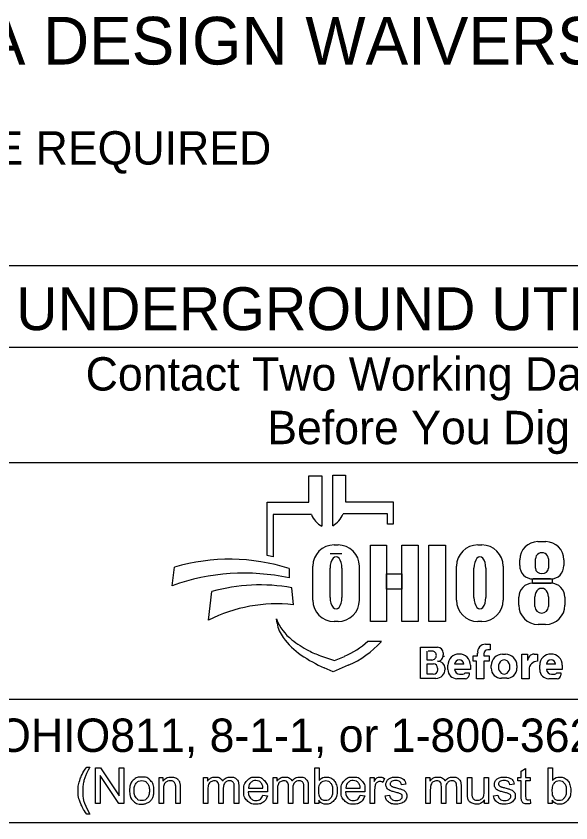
# Model space of a CAD drawing. Extents: x 0 to 34, y 0 to 22.
# Drawn here: x 2.506 to 4.831, y 2.01 to 5.395 of the extents above; entities that cross this region are included whole.
import ezdxf

# ---------------------------------------------------------------- set-up
doc = ezdxf.new("R2010")
doc.units = 0
doc.layers.add('SH_Data', color=7, linetype='Continuous')
doc.layers.add('SH_Text', color=7, linetype='Continuous')

msp = doc.modelspace()

# ---------------------------------------------------------------- linework, layer by layer
at = {"layer": 'SH_Data'}
for p, q in [((6.6275, 4.3472), (2.3775, 4.3472)), ((2.3775, 4.0056), (6.6275, 4.0056)), ((2.3775, 3.5222), (6.6275, 3.5222)), ((6.6275, 2.5276), (2.3775, 2.5276)), ((6.6275, 2.0097), (2.3775, 2.0097))]:
    msp.add_line(p, q, dxfattribs=at)
at = {"layer": 'SH_Text'}
for p, q in [((3.7335, 3.3552), (3.7335, 3.4667)), ((3.7335, 3.4667), (3.7872, 3.4667)), ((3.7872, 3.4667), (3.7872, 3.2546)), ((3.8329, 3.2569), (3.8329, 3.469)), ((3.8329, 3.469), (3.8865, 3.469)), ((3.8865, 3.469), (3.8865, 3.3575)), ((3.5576, 3.1313), (3.5576, 3.3552)), ((3.5576, 3.3552), (3.7335, 3.3552)), ((3.8865, 3.3575), (4.0857, 3.3575)), ((4.0857, 3.3575), (4.0857, 3.2637)), ((3.5828, 3.3038), (3.5828, 3.1269)), ((3.7439, 3.3038), (3.5828, 3.3038)), ((4.0625, 3.3061), (3.8761, 3.3061)), ((4.0625, 3.2637), (4.0625, 3.3061)), ((4.0857, 3.2637), (4.0625, 3.2637)), ((4.6931, 3.19), (4.7258, 3.19)), ((3.8385, 3.176), (3.8551, 3.176)), ((4.4416, 3.176), (4.4581, 3.176)), ((3.8718, 3.139), (3.822, 3.139)), ((4.683, 3.078), (4.683, 3.1173)), ((4.7371, 3.1173), (4.7371, 3.078)), ((3.1602, 3.005), (3.1696, 3.0831)), ((3.7491, 2.9445), (3.7491, 3.0865)), ((3.9445, 3.0865), (3.9445, 2.9445)), ((4.3521, 2.9445), (4.3521, 3.0865)), ((4.5476, 3.0865), (4.5476, 2.9445)), ((4.6168, 3.0894), (4.6168, 3.1137)), ((4.8022, 3.1137), (4.8022, 3.0894)), ((3.6509, 3.0766), (3.6509, 3.0378)), ((3.822, 2.9559), (3.822, 3.0783)), ((3.8718, 3.0783), (3.8718, 2.9559)), ((4.425, 2.9559), (4.425, 3.0783)), ((4.4748, 3.0783), (4.4748, 2.9559)), ((4.671, 3.0151), (4.7483, 3.0151)), ((4.7462, 3.0334), (4.6728, 3.0334)), ((3.312, 2.8605), (3.3267, 2.9806)), ((3.6608, 2.996), (3.6671, 2.9251)), ((4.6131, 2.9232), (4.6131, 2.9572)), ((4.6806, 2.9172), (4.6806, 2.9581)), ((4.7374, 2.9581), (4.7374, 2.9172)), ((4.8062, 2.9572), (4.8062, 2.9232)), ((3.5997, 2.8476), (3.5967, 2.8655)), ((3.8551, 2.8551), (3.8385, 2.8551)), ((4.4581, 2.8551), (4.4416, 2.8551)), ((4.7252, 2.8422), (4.6941, 2.8422)), ((3.98, 2.7717), (4.0375, 2.7717)), ((4.2013, 2.6159), (4.2013, 2.7467)), ((4.2013, 2.7467), (4.2725, 2.7467)), ((4.4739, 2.7595), (4.4934, 2.7595)), ((4.4934, 2.7595), (4.4934, 2.7365)), ((3.7816, 2.7113), (3.841, 2.6908)), ((4.2293, 2.6932), (4.2293, 2.7301)), ((4.2545, 2.7301), (4.2332, 2.7301)), ((4.2963, 2.7229), (4.2963, 2.715)), ((4.4213, 2.6881), (4.4213, 2.7111)), ((4.4213, 2.7111), (4.4406, 2.7111)), ((4.4406, 2.7111), (4.4406, 2.7215)), ((4.4667, 2.7195), (4.4667, 2.7111)), ((4.4667, 2.7111), (4.4883, 2.7111)), ((4.4934, 2.736), (4.4832, 2.736)), ((4.4883, 2.7111), (4.4883, 2.6881)), ((4.5451, 2.7177), (4.5573, 2.7177)), ((4.6254, 2.6147), (4.6254, 2.7174)), ((4.6254, 2.7174), (4.6499, 2.7174)), ((4.6499, 2.7174), (4.6499, 2.6906)), ((4.6772, 2.7174), (4.691, 2.7174)), ((4.691, 2.7174), (4.691, 2.6878)), ((3.841, 2.6908), (3.8821, 2.7086)), ((4.2487, 2.6932), (4.2293, 2.6932)), ((4.2293, 2.6338), (4.2293, 2.6766)), ((4.2293, 2.6766), (4.2548, 2.6766)), ((4.3824, 2.6751), (4.3439, 2.6751)), ((4.4362, 2.6881), (4.4213, 2.6881)), ((4.4362, 2.6147), (4.4362, 2.6881)), ((4.4883, 2.6881), (4.4667, 2.6881)), ((4.4667, 2.6881), (4.4667, 2.6147)), ((4.7674, 2.6751), (4.7288, 2.6751)), ((3.835, 2.6438), (3.7976, 2.6603)), ((3.8983, 2.6713), (3.835, 2.6438)), ((4.2729, 2.6585), (4.2729, 2.6522)), ((4.3043, 2.6556), (4.3043, 2.6553)), ((4.3159, 2.6527), (4.3159, 2.6711)), ((4.4104, 2.6535), (4.344, 2.6535)), ((4.4104, 2.6711), (4.4104, 2.6535)), ((4.4973, 2.6591), (4.4973, 2.6698)), ((4.6051, 2.6698), (4.6051, 2.6591)), ((4.6559, 2.6529), (4.6559, 2.6147)), ((4.7008, 2.6527), (4.7008, 2.6711)), ((4.7953, 2.6535), (4.7289, 2.6535)), ((4.7953, 2.6711), (4.7953, 2.6535)), ((4.265, 2.6159), (4.2013, 2.6159)), ((4.2546, 2.6338), (4.2293, 2.6338)), ((4.3892, 2.6147), (4.3538, 2.6147)), ((4.3649, 2.6342), (4.379, 2.6342)), ((4.3876, 2.6398), (4.4045, 2.6398)), ((4.4045, 2.6398), (4.4045, 2.63)), ((4.4667, 2.6147), (4.4362, 2.6147)), ((4.5623, 2.6163), (4.5401, 2.6163)), ((4.6559, 2.6147), (4.6254, 2.6147)), ((4.7742, 2.6147), (4.7388, 2.6147)), ((4.7498, 2.6342), (4.7639, 2.6342)), ((4.7725, 2.6398), (4.7894, 2.6398)), ((4.7894, 2.6398), (4.7894, 2.63))]:
    msp.add_line(p, q, dxfattribs=at)
for points in [[(3.991, 3.175), (4.0589, 3.175), (4.0589, 2.855), (3.991, 2.855)], [(4.1231, 3.175), (4.1911, 3.175), (4.1911, 2.855), (4.1231, 2.855)], [(4.2364, 3.175), (4.3052, 3.175), (4.3052, 2.855), (4.2364, 2.855)], [(4.0589, 3.0551), (4.1231, 3.0551), (4.1231, 2.9911), (4.0589, 2.9911)], [(4.6706, 3.0334), (4.7523, 3.0334), (4.7523, 3.015), (4.6706, 3.015)]]:
    msp.add_lwpolyline(points, close=True, dxfattribs=at)
for points in [[(2.8021, 2.2435), (2.8153, 2.2435)], [(2.8389, 2.0908), (2.8389, 2.241), (2.8592, 2.241), (2.9382, 2.123), (2.9382, 2.241), (2.9572, 2.241), (2.9572, 2.0908), (2.9369, 2.0908), (2.8579, 2.2088), (2.8579, 2.0908), (2.8389, 2.0908)], [(3.7743, 2.0908), (3.7573, 2.0908), (3.7573, 2.241), (3.7757, 2.241), (3.7757, 2.1875)], [(4.6233, 2.1227), (4.6233, 2.1854), (4.6097, 2.1854), (4.6097, 2.1997), (4.6233, 2.1997), (4.6233, 2.2266), (4.6417, 2.2377), (4.6417, 2.1997), (4.6601, 2.1997), (4.6601, 2.1854), (4.6417, 2.1854), (4.6417, 2.1216)], [(4.7534, 2.0908), (4.7363, 2.0908), (4.7363, 2.241), (4.7548, 2.241), (4.7548, 2.1875)], [(3.1048, 2.0908), (3.1048, 2.1997), (3.1214, 2.1997), (3.1214, 2.1842)], [(3.2912, 2.0908), (3.2912, 2.1997), (3.3077, 2.1997), (3.3077, 2.1843)], [(3.5826, 2.0908), (3.5826, 2.1997), (3.5991, 2.1997), (3.5991, 2.1843)], [(3.9904, 2.0908), (3.9904, 2.1997), (4.007, 2.1997), (4.007, 2.1832)], [(4.0495, 2.1962), (4.043, 2.1791)], [(4.1394, 2.1715), (4.1213, 2.1691)], [(4.2236, 2.0908), (4.2236, 2.1997), (4.2401, 2.1997), (4.2401, 2.1843)], [(4.3979, 2.1323), (4.3979, 2.1997), (4.4164, 2.1997), (4.4164, 2.1393)], [(4.4676, 2.1414), (4.4676, 2.1997), (4.4861, 2.1997), (4.4861, 2.0908), (4.4696, 2.0908)], [(4.594, 2.1715), (4.5759, 2.1691)], [(3.1233, 2.1502), (3.1233, 2.0908), (3.1048, 2.0908)], [(3.1932, 2.1577), (3.1932, 2.0908), (3.1748, 2.0908), (3.1748, 2.157)], [(3.3097, 2.1472), (3.3097, 2.0908), (3.2912, 2.0908)], [(3.3743, 2.154), (3.3743, 2.0908), (3.3559, 2.0908), (3.3559, 2.1615)], [(3.4388, 2.1655), (3.4388, 2.0908), (3.4203, 2.0908), (3.4203, 2.1593)], [(3.56, 2.1405), (3.4788, 2.1405)], [(3.4799, 2.1556), (3.5406, 2.1556)], [(3.601, 2.1472), (3.601, 2.0908), (3.5826, 2.0908)], [(3.6657, 2.154), (3.6657, 2.0908), (3.6473, 2.0908), (3.6473, 2.1615)], [(3.7301, 2.1655), (3.7301, 2.0908), (3.7117, 2.0908), (3.7117, 2.1593)], [(3.968, 2.1405), (3.8868, 2.1405)], [(3.8879, 2.1556), (3.9486, 2.1556)], [(4.0088, 2.1478), (4.0088, 2.0908), (3.9904, 2.0908)], [(4.242, 2.1472), (4.242, 2.0908), (4.2236, 2.0908)], [(4.3067, 2.154), (4.3067, 2.0908), (4.2883, 2.0908), (4.2883, 2.1615)], [(4.3711, 2.1655), (4.3711, 2.0908), (4.3527, 2.0908), (4.3527, 2.1593)], [(3.5404, 2.126), (3.5595, 2.1236)], [(3.7743, 2.1044), (3.7743, 2.0908)], [(3.9484, 2.126), (3.9675, 2.1236)], [(4.053, 2.1233), (4.0712, 2.1262)], [(4.4696, 2.0908), (4.4696, 2.1069)], [(4.5076, 2.1233), (4.5258, 2.1262)], [(4.6601, 2.1073), (4.6628, 2.091)], [(4.7534, 2.1044), (4.7534, 2.0908)], [(2.8153, 2.0466), (2.8021, 2.0466)]]:
    msp.add_lwpolyline(points, dxfattribs=at)
for centre, radius, start, end in [((3.8353, 3.3405), 0.0985, 201.9296, 240.7469), ((3.7847, 3.3429), 0.0985, 299.2531, 338.0704), ((4.6931, 3.1137), 0.0763, 90, 180), ((4.7258, 3.1137), 0.0763, 0, 90), ((3.8385, 3.0865), 0.0895, 90, 180), ((3.8551, 3.0865), 0.0895, 0, 90), ((4.4416, 3.0865), 0.0895, 90, 180), ((4.4581, 3.0865), 0.0895, 0, 90), ((3.3997, 2.2971), 0.8191, 72.1402, 106.3144), ((3.4295, 2.3223), 0.8191, 79.2074, 81.0007), ((4.6728, 3.0894), 0.056, 180, 270), ((4.7462, 3.0894), 0.056, 270, 0), ((3.4628, 2.1659), 0.8919, 77.8238, 109.8274), ((4.671, 2.9572), 0.0579, 90, 180), ((4.7483, 2.9572), 0.0579, 0, 90), ((3.5267, 2.2763), 0.7322, 79.44, 105.8467), ((3.5987, 2.2931), 0.6357, 83.8248, 116.8021), ((3.8385, 2.9445), 0.0895, 180, 270), ((3.8551, 2.9445), 0.0895, 270, 0), ((4.4416, 2.9445), 0.0895, 180, 270), ((4.4581, 2.9445), 0.0895, 270, 0), ((4.6941, 2.9232), 0.081, 180, 270), ((4.7252, 2.9232), 0.081, 270, 0), ((3.7841, 2.9376), 0.2008, 201.0457, 232.5314), ((3.741, 2.8717), 0.1433, 189.6817, 216.0884), ((3.8747, 2.9691), 0.3088, 216.0884, 235.7167), ((3.9766, 3.1888), 0.5173, 232.5314, 241.794), ((3.7387, 3.0391), 0.3602, 293.4582, 312.0712), ((3.7387, 3.0391), 0.401, 293.4582, 317.8286), ((4.2725, 2.7229), 0.0238, 0, 90), ((4.4739, 2.7259), 0.0335, 90, 187.5187), ((4.0412, 3.2134), 0.6044, 235.7167, 246.2325), ((3.8914, 3.03), 0.3371, 241.794, 250.9821), ((4.2487, 2.7119), 0.0187, 270, 2.0582), ((4.2505, 2.7132), 0.0169, 357.8325, 90), ((4.2721, 2.7122), 0.0243, 270, 6.6529), ((4.2827, 2.7107), 0.0175, 347.4023, 0), ((4.3631, 2.6711), 0.0473, 0, 180), ((4.4832, 2.7195), 0.0165, 90, 180), ((4.5451, 2.6698), 0.0478, 90, 180), ((4.5573, 2.6698), 0.0478, 0, 90), ((4.6768, 2.6906), 0.0269, 89.2449, 180), ((4.7481, 2.6711), 0.0473, 0, 180), ((4.2548, 2.6585), 0.0181, 0, 90), ((4.2722, 2.6558), 0.0321, 4.0748, 90), ((4.3632, 2.6741), 0.0193, 2.9632, 177.0368), ((4.6908, 2.6529), 0.0349, 89.6033, 180), ((4.7481, 2.6741), 0.0193, 2.9632, 177.0368), ((4.2546, 2.6522), 0.0184, 270, 0), ((4.265, 2.6553), 0.0393, 270, 0), ((4.2714, 2.6556), 0.033, 0, 11.7502), ((4.3538, 2.6527), 0.038, 180, 270), ((4.3649, 2.6552), 0.021, 184.827, 270), ((4.5401, 2.6591), 0.0428, 180, 270), ((4.5623, 2.6591), 0.0428, 270, 0), ((4.7388, 2.6527), 0.038, 180, 270), ((4.7498, 2.6552), 0.021, 184.827, 270), ((4.379, 2.6436), 0.00938, 270, 335.9979), ((4.3892, 2.63), 0.0152, 270, 0), ((4.7639, 2.6436), 0.00938, 270, 335.9979), ((4.7742, 2.63), 0.0152, 270, 0)]:
    msp.add_arc(centre, radius, start, end, dxfattribs=at)
for centre, major_axis, ratio, start_param, end_param in [((3.8469, 3.0783), (0, 0.0484), 0.514403, 4.712389, 7.853982), ((4.4499, 3.0783), (0, 0.0484), 0.514403, 4.712389, 7.853982), ((4.71, 3.1173), (0.0271, 0), 0.969373, 0, 3.141593), ((4.71, 3.078), (0.0271, 0), 0.818453, 3.141593, 6.283185), ((4.709, 2.9581), (0, 0.0358), 0.794529, 4.712389, 7.853982), ((3.8469, 2.9559), (0, 0.0484), 0.514403, 1.570796, 4.712389), ((4.4499, 2.9559), (0, 0.0484), 0.514403, 1.570796, 4.712389), ((4.709, 2.9172), (0.0284, 0), 0.959837, 3.141593, 6.283185), ((4.5517, 2.6644), (0, 0.029), 0.832186, 4.712389, 7.853982), ((4.5517, 2.6644), (0, 0.0302), 0.797287, 1.570796, 4.712389)]:
    msp.add_ellipse(centre, major_axis=major_axis, ratio=ratio, start_param=start_param, end_param=end_param, dxfattribs=at)
for points in [[(2.8021, 2.0466), (2.7869, 2.0659), (2.7763, 2.0917), (2.7657, 2.1175), (2.7657, 2.1452), (2.7657, 2.1695), (2.7736, 2.1919), (2.7829, 2.2178), (2.8021, 2.2435)], [(2.8153, 2.2435), (2.8029, 2.2222), (2.7989, 2.2131), (2.7927, 2.1989), (2.7891, 2.1836), (2.7847, 2.1644), (2.7847, 2.1451), (2.7847, 2.0958), (2.8153, 2.0466)], [(2.9814, 2.1452), (2.9814, 2.1754), (2.9981, 2.19), (3.0122, 2.2021), (3.0323, 2.2021), (3.0547, 2.2021), (3.069, 2.1874), (3.0832, 2.1727), (3.0832, 2.1468), (3.0832, 2.1258), (3.0769, 2.1138), (3.0706, 2.1017), (3.0586, 2.0951), (3.0466, 2.0884), (3.0323, 2.0884), (3.0095, 2.0884), (2.9954, 2.1031), (2.9814, 2.1177), (2.9814, 2.1452)], [(3.1214, 2.1842), (3.1334, 2.2021), (3.156, 2.2021), (3.1659, 2.2021), (3.1741, 2.1985), (3.1823, 2.195), (3.1864, 2.1893), (3.1905, 2.1835), (3.1922, 2.1756), (3.1932, 2.1705), (3.1932, 2.1577)], [(3.3077, 2.1843), (3.3128, 2.1923), (3.3214, 2.1972), (3.3299, 2.2021), (3.3407, 2.2021), (3.3528, 2.2021), (3.3606, 2.197), (3.3683, 2.192), (3.3715, 2.183), (3.3844, 2.2021), (3.4051, 2.2021), (3.4213, 2.2021), (3.43, 2.1931), (3.4388, 2.1841), (3.4388, 2.1655)], [(3.5595, 2.1236), (3.555, 2.1069), (3.5428, 2.0976), (3.5306, 2.0884), (3.5117, 2.0884), (3.4878, 2.0884), (3.4738, 2.1031), (3.4598, 2.1178), (3.4598, 2.1443), (3.4598, 2.1718), (3.474, 2.1869), (3.4881, 2.2021), (3.5106, 2.2021), (3.5324, 2.2021), (3.5463, 2.1872), (3.5601, 2.1724), (3.5601, 2.1454), (3.5601, 2.1438), (3.56, 2.1405)], [(3.5991, 2.1843), (3.6042, 2.1923), (3.6127, 2.1972), (3.6212, 2.2021), (3.6321, 2.2021), (3.6442, 2.2021), (3.6519, 2.197), (3.6597, 2.192), (3.6628, 2.183), (3.6758, 2.2021), (3.6965, 2.2021), (3.7127, 2.2021), (3.7214, 2.1931), (3.7301, 2.1841), (3.7301, 2.1655)], [(3.7757, 2.1875), (3.7874, 2.2021), (3.8055, 2.2021), (3.8155, 2.2021), (3.8245, 2.198), (3.8335, 2.194), (3.8392, 2.1867), (3.845, 2.1793), (3.8483, 2.169), (3.8516, 2.1587), (3.8516, 2.1469), (3.8516, 2.1189), (3.8378, 2.1037), (3.8239, 2.0884), (3.8046, 2.0884), (3.7853, 2.0884), (3.7743, 2.1044)], [(3.9675, 2.1236), (3.963, 2.1069), (3.9508, 2.0976), (3.9386, 2.0884), (3.9196, 2.0884), (3.8958, 2.0884), (3.8818, 2.1031), (3.8678, 2.1178), (3.8678, 2.1443), (3.8678, 2.1718), (3.882, 2.1869), (3.8961, 2.2021), (3.9186, 2.2021), (3.9404, 2.2021), (3.9543, 2.1872), (3.9681, 2.1724), (3.9681, 2.1454), (3.9681, 2.1438), (3.968, 2.1405)], [(4.007, 2.1832), (4.0133, 2.1947), (4.0187, 2.1984), (4.0241, 2.2021), (4.0305, 2.2021), (4.0398, 2.2021), (4.0495, 2.1962)], [(4.0712, 2.1262), (4.0727, 2.1152), (4.0798, 2.1094), (4.0868, 2.1035), (4.0995, 2.1035), (4.1122, 2.1035), (4.1184, 2.1087), (4.1245, 2.1139), (4.1245, 2.1209), (4.1245, 2.1271), (4.1191, 2.1307), (4.1153, 2.1332), (4.1002, 2.137), (4.0799, 2.1421), (4.072, 2.1458), (4.0642, 2.1496), (4.0601, 2.1562), (4.0561, 2.1628), (4.0561, 2.1707), (4.0561, 2.178), (4.0594, 2.1842), (4.0628, 2.1904), (4.0685, 2.1945), (4.0728, 2.1977), (4.0803, 2.1999), (4.0877, 2.2021), (4.0962, 2.2021), (4.109, 2.2021), (4.1187, 2.1984), (4.1284, 2.1947), (4.133, 2.1884), (4.1377, 2.1821), (4.1394, 2.1715)], [(4.2401, 2.1843), (4.2452, 2.1923), (4.2537, 2.1972), (4.2622, 2.2021), (4.2731, 2.2021), (4.2852, 2.2021), (4.2929, 2.197), (4.3007, 2.192), (4.3038, 2.183), (4.3168, 2.2021), (4.3375, 2.2021), (4.3537, 2.2021), (4.3624, 2.1931), (4.3711, 2.1841), (4.3711, 2.1655)], [(4.5258, 2.1262), (4.5273, 2.1152), (4.5343, 2.1094), (4.5414, 2.1035), (4.554, 2.1035), (4.5668, 2.1035), (4.5729, 2.1087), (4.5791, 2.1139), (4.5791, 2.1209), (4.5791, 2.1271), (4.5736, 2.1307), (4.5698, 2.1332), (4.5548, 2.137), (4.5345, 2.1421), (4.5266, 2.1458), (4.5188, 2.1496), (4.5147, 2.1562), (4.5107, 2.1628), (4.5107, 2.1707), (4.5107, 2.178), (4.514, 2.1842), (4.5173, 2.1904), (4.5231, 2.1945), (4.5274, 2.1977), (4.5348, 2.1999), (4.5423, 2.2021), (4.5508, 2.2021), (4.5636, 2.2021), (4.5733, 2.1984), (4.583, 2.1947), (4.5876, 2.1884), (4.5922, 2.1821), (4.594, 2.1715)], [(4.7548, 2.1875), (4.7664, 2.2021), (4.7846, 2.2021), (4.7946, 2.2021), (4.8036, 2.198), (4.8125, 2.194), (4.8183, 2.1867), (4.8241, 2.1793), (4.8274, 2.169), (4.8306, 2.1587), (4.8306, 2.1469), (4.8306, 2.1189), (4.8168, 2.1037), (4.803, 2.0884), (4.7836, 2.0884), (4.7644, 2.0884), (4.7534, 2.1044)], [(3.0003, 2.1452), (3.0003, 2.1243), (3.0094, 2.1139), (3.0185, 2.1035), (3.0323, 2.1035), (3.046, 2.1035), (3.0551, 2.114), (3.0642, 2.1244), (3.0642, 2.1459), (3.0642, 2.166), (3.0551, 2.1764), (3.0459, 2.1868), (3.0323, 2.1868), (3.0185, 2.1868), (3.0094, 2.1765), (3.0003, 2.1661), (3.0003, 2.1452)], [(3.1748, 2.157), (3.1748, 2.1682), (3.1726, 2.1738), (3.1705, 2.1794), (3.165, 2.1827), (3.1595, 2.186), (3.1521, 2.186), (3.1404, 2.186), (3.1318, 2.1786), (3.1233, 2.1711), (3.1233, 2.1502)], [(3.3559, 2.1615), (3.3559, 2.1738), (3.3514, 2.1799), (3.3469, 2.186), (3.3366, 2.186), (3.3288, 2.186), (3.3222, 2.1819), (3.3156, 2.1779), (3.3126, 2.17), (3.3097, 2.1621), (3.3097, 2.1472)], [(3.4203, 2.1593), (3.4203, 2.1704), (3.4185, 2.1752), (3.4168, 2.1801), (3.412, 2.1831), (3.4073, 2.186), (3.401, 2.186), (3.3895, 2.186), (3.3819, 2.1784), (3.3743, 2.1708), (3.3743, 2.154)], [(3.5406, 2.1556), (3.5394, 2.1694), (3.5337, 2.1763), (3.5249, 2.187), (3.5108, 2.187), (3.4981, 2.187), (3.4894, 2.1784), (3.4808, 2.1699), (3.4799, 2.1556)], [(3.6473, 2.1615), (3.6473, 2.1738), (3.6428, 2.1799), (3.6383, 2.186), (3.628, 2.186), (3.6202, 2.186), (3.6136, 2.1819), (3.607, 2.1779), (3.604, 2.17), (3.601, 2.1621), (3.601, 2.1472)], [(3.7117, 2.1593), (3.7117, 2.1704), (3.7099, 2.1752), (3.7081, 2.1801), (3.7034, 2.1831), (3.6987, 2.186), (3.6923, 2.186), (3.6809, 2.186), (3.6733, 2.1784), (3.6657, 2.1708), (3.6657, 2.154)], [(3.7741, 2.1461), (3.7741, 2.1265), (3.7794, 2.1178), (3.7881, 2.1035), (3.8029, 2.1035), (3.815, 2.1035), (3.8238, 2.114), (3.8326, 2.1245), (3.8326, 2.1453), (3.8326, 2.1667), (3.8241, 2.1768), (3.8157, 2.187), (3.8038, 2.187), (3.7917, 2.187), (3.7829, 2.1764), (3.7741, 2.1659), (3.7741, 2.1461)], [(3.9486, 2.1556), (3.9474, 2.1694), (3.9417, 2.1763), (3.9328, 2.187), (3.9188, 2.187), (3.9061, 2.187), (3.8974, 2.1784), (3.8888, 2.1699), (3.8879, 2.1556)], [(4.043, 2.1791), (4.0363, 2.1831), (4.0295, 2.1831), (4.0235, 2.1831), (4.0187, 2.1794), (4.0139, 2.1758), (4.0119, 2.1693), (4.0088, 2.1595), (4.0088, 2.1478)], [(4.1213, 2.1691), (4.1201, 2.1775), (4.1142, 2.1822), (4.1083, 2.187), (4.0975, 2.187), (4.0848, 2.187), (4.0794, 2.1827), (4.0739, 2.1785), (4.0739, 2.1729), (4.0739, 2.1693), (4.0762, 2.1664), (4.0785, 2.1635), (4.0833, 2.1615), (4.086, 2.1605), (4.0996, 2.1568), (4.1192, 2.1516), (4.1269, 2.1482), (4.1347, 2.1449), (4.1391, 2.1386), (4.1435, 2.1322), (4.1435, 2.1228), (4.1435, 2.1136), (4.1381, 2.1055), (4.1327, 2.0973), (4.1226, 2.0929), (4.1124, 2.0884), (4.0996, 2.0884), (4.0784, 2.0884), (4.0672, 2.0972), (4.0561, 2.106), (4.053, 2.1233)], [(4.2883, 2.1615), (4.2883, 2.1738), (4.2838, 2.1799), (4.2793, 2.186), (4.269, 2.186), (4.2612, 2.186), (4.2546, 2.1819), (4.248, 2.1779), (4.245, 2.17), (4.242, 2.1621), (4.242, 2.1472)], [(4.3527, 2.1593), (4.3527, 2.1704), (4.3509, 2.1752), (4.3491, 2.1801), (4.3444, 2.1831), (4.3397, 2.186), (4.3333, 2.186), (4.3219, 2.186), (4.3143, 2.1784), (4.3067, 2.1708), (4.3067, 2.154)], [(4.5759, 2.1691), (4.5747, 2.1775), (4.5688, 2.1822), (4.5629, 2.187), (4.5521, 2.187), (4.5394, 2.187), (4.5339, 2.1827), (4.5285, 2.1785), (4.5285, 2.1729), (4.5285, 2.1693), (4.5308, 2.1664), (4.533, 2.1635), (4.5378, 2.1615), (4.5406, 2.1605), (4.5542, 2.1568), (4.5737, 2.1516), (4.5815, 2.1482), (4.5893, 2.1449), (4.5937, 2.1386), (4.5981, 2.1322), (4.5981, 2.1228), (4.5981, 2.1136), (4.5927, 2.1055), (4.5873, 2.0973), (4.5772, 2.0929), (4.567, 2.0884), (4.5542, 2.0884), (4.5329, 2.0884), (4.5218, 2.0972), (4.5107, 2.106), (4.5076, 2.1233)], [(4.7532, 2.1461), (4.7532, 2.1265), (4.7585, 2.1178), (4.7672, 2.1035), (4.782, 2.1035), (4.7941, 2.1035), (4.8029, 2.114), (4.8116, 2.1245), (4.8116, 2.1453), (4.8116, 2.1667), (4.8032, 2.1768), (4.7948, 2.187), (4.7828, 2.187), (4.7708, 2.187), (4.762, 2.1764), (4.7532, 2.1659), (4.7532, 2.1461)], [(3.4788, 2.1405), (3.4799, 2.1226), (3.489, 2.113), (3.4981, 2.1035), (3.5117, 2.1035), (3.5219, 2.1035), (3.5291, 2.1089), (3.5362, 2.1142), (3.5404, 2.126)], [(3.8868, 2.1405), (3.8879, 2.1226), (3.897, 2.113), (3.9061, 2.1035), (3.9197, 2.1035), (3.9299, 2.1035), (3.937, 2.1089), (3.9442, 2.1142), (3.9484, 2.126)], [(4.4164, 2.1393), (4.4164, 2.1249), (4.4175, 2.1199), (4.4192, 2.1126), (4.4249, 2.1085), (4.4305, 2.1043), (4.4388, 2.1043), (4.4471, 2.1043), (4.4543, 2.1086), (4.4616, 2.1128), (4.4646, 2.1201), (4.4676, 2.1275), (4.4676, 2.1414)], [(4.4696, 2.1069), (4.4569, 2.0884), (4.4351, 2.0884), (4.4255, 2.0884), (4.4171, 2.0921), (4.4088, 2.0958), (4.4047, 2.1014), (4.4007, 2.107), (4.3991, 2.1151), (4.3979, 2.1205), (4.3979, 2.1323)], [(4.6628, 2.091), (4.655, 2.0893), (4.6488, 2.0893), (4.6388, 2.0893), (4.6333, 2.0925), (4.6278, 2.0957), (4.6255, 2.1009), (4.6233, 2.1061), (4.6233, 2.1227)], [(4.6417, 2.1216), (4.6417, 2.1137), (4.6427, 2.1114), (4.6436, 2.1092), (4.6458, 2.1078), (4.648, 2.1065), (4.6521, 2.1065), (4.6551, 2.1065), (4.6601, 2.1073)]]:
    msp.add_open_spline(points, degree=3, dxfattribs=at)

# ---------------------------------------------------------------- texts
for s, height, p in [('ADA DESIGN WAIVERS', 0.2, (1.9944, 5.1925)), ('NONE REQUIRED', 0.14, (1.9944, 4.7725)), ('UNDERGROUND UTILITIES', 0.18, (2.5057, 4.0775)), ('Contact Two Working Days', 0.14, (2.7972, 3.824)), ('Before You Dig', 0.14, (3.5583, 3.599)), ('OHIO811, 8-1-1, or 1-800-362-2764', 0.14, (2.422, 2.3075))]:
    msp.add_text(s, height=height, dxfattribs=at).set_placement(p)

doc.saveas('drawing.dxf')
